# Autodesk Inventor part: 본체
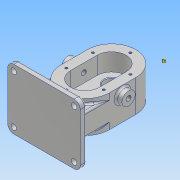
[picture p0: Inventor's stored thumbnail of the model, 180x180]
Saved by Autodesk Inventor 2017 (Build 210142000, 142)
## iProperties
Part Number: 본체
Material: 알루미늄 6061
Document SubType Name: Modeling
Designer: 222
Density: 2.7 g/cm^3
Appearance: 알루미늄 - 평지
Mass: 1442.14 g
Surface Area: 789.865 cm^2
Volume: 534.127 cm^3
Author: 222
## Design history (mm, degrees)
sketch "스케치1"
  geometry: L1 (-40, 0)-(-40, -44); L2 (40, 0)-(40, -44); A1 r 40 centre (0, 0) between (40, 0) and (-40, 0); A2 r 40 centre (0, -44) between (-40, -44) and (40, -44); 1 further point
  constraints: 4 end point, 4 point on circle, 4 tangent, 2 centre point, 1 coincident, 1 vertical alignment
  dimensions: "d7" = 80 diameter of A2; "d8" = 80 diameter of A1; "d9" = 124 dimension on A2 A1
extrude "돌출1" new body sketch "스케치1" distance "d10" = 53; taper "d11" = 0 deg
sketch "스케치2"
  geometry: L1 (-24, 0)-(-24, -44); L2 (24, 0)-(24, -44); A1 r 24 centre (0, 0) between (24, 0) and (-24, 0); A2 r 24 centre (0, -44) between (-24, -44) and (24, -44); 1 further point
  constraints: 4 end point, 4 point on circle, 3 tangent, 2 centre point, 1 coincident, 1 vertical, 1 vertical alignment
  dimensions: "d12" = 48 diameter of A1; "d13" = 48 diameter of A2; "d14" = 92 dimension on A2 A1
extrude "돌출2" cut sketch "스케치2" distance "d15" = 29; taper "d16" = 0 deg
node "작업 평면1"
sketch "스케치4"
  geometry: C1 r 19 at (0, 0); 1 further point
  constraints: 1 centre point, 1 coincident
  dimensions: "d18" = 38 diameter of C1
extrude "돌출3" join sketch "스케치4" distance "d19" = 17; taper "d20" = 0 deg
sketch "스케치5"
  geometry: C1 r 12.5 at (0, 0); 1 further point
  constraints: 1 centre point, 1 coincident
  dimensions: "d21" = 25 diameter of C1
extrude "돌출4" cut sketch "스케치5" distance "d22" = 15; taper "d23" = 0 deg
sketch "스케치6"
  geometry: C1 r 8.5 at (0, 0); 1 further point
  constraints: 1 centre point, 1 coincident
  dimensions: "d24" = 17 diameter of C1
extrude "돌출5" cut sketch "스케치6" stored distance "d25" = 15; taper "d26" = 0 deg
sketch "스케치7"
  geometry: L1 (24, 0)-(24, -44) reference; L2 (-24, -44)-(-24, 0) reference; L3 (-40, 0)-(-40, -44) reference; L4 (40, -44)-(40, 0) reference; C1 r 12.5 at (0, -44); A1 r 24 centre (0, 0) between (24, 0) and (-24, 0) reference; A2 r 24 centre (0, -44) between (-24, -44) and (24, -44) reference; A3 r 40 centre (0, 0) between (40, 0) and (-40, 0) reference; A4 r 40 centre (0, -44) between (-40, -44) and (40, -44) reference; 1 further point
  constraints: 1 centre point, 1 coincident
  dimensions: "d27" = 25 diameter of C1
extrude "돌출6" cut sketch "스케치7" distance "d28" = 15; taper "d29" = 0 deg
sketch "스케치8"
  geometry: C1 r 14 at (0, 0); 1 further point
  constraints: 1 centre point, 1 coincident
  dimensions: "d30" = 28 diameter of C1
extrude "돌출7" cut sketch "스케치8" distance "d31" = 7.3; taper "d32" = 0 deg
node "작업 평면3"
  node "작업 평면2"
sketch "스케치9"
  geometry: L1 (60, 83)-(-60, 83); L2 (-60, 83)-(-60, -17); L3 (-60, -17)-(60, -17); L4 (60, -17)-(60, 83); L5 (-19, -17)-(19, -17) reference; 3 further points
  constraints: 8 end point, 3 midpoint, 2 parallel, 1 coincident, 1 horizontal, 1 perpendicular
  dimensions: "d34" = 120 distance of L3.end L2.end; "d35" = 100 distance of L2.end L1.end
extrude "돌출8" join sketch "스케치9" distance "d36" = 10; taper "d37" = 0 deg
sketch "스케치10"
  geometry: L1 (-40, -45)-(40, -45); L2 (40, -45)-(40, -8); L3 (40, -8)-(-40, -8); L4 (-40, -8)-(-40, -45); L5 (60, 17)-(-60, 17) reference; 3 further points
  constraints: 8 end point, 2 coincident, 2 parallel, 1 horizontal, 1 midpoint, 1 perpendicular, 1 vertical alignment
  dimensions: "d40" = 80 distance of L3.end L2.end; "d41" = 37 distance of L2.end L1.end; "d42" = 25 distance between parallel lines of L5 L3
extrude "돌출9" join sketch "스케치10" stored distance "d43" = 10; taper "d44" = 0 deg
fillet "모깎기1" dims "d45" = 10
sketch "스케치11"
  geometry: L1 (0, 44)-(-53, 44) reference; L2 (-53, 0)-(-53, 44) reference; L3 (-45, 0)-(-53, 0) reference; L4 (-45, -58)-(-45, 0) reference; L5 (-83, -58)-(-45, -58) reference; L6 (-83, -68)-(-83, -58) reference; L7 (17, -68)-(-83, -68) reference; L8 (17, -58)-(17, -68) reference; L9 (-8, -58)-(17, -58) reference; L10 (-45, -58)-(-8, -58) reference; L11 (0, 44)-(0, 0) reference; L12 (0, 0)-(-8, 0) reference; L13 (-8, 0)-(-8, -58) reference; C1 r 11 at (-39, 22)
  constraints: 1 centre point
  dimensions: "d46" = 22 diameter of C1; "d47" = 22 distance from line of C1.centre L1; "d48" = 14 distance from line of L2 C1.centre
extrude "돌출10" join sketch "스케치11" distance "d49" = 10; taper "d50" = 0 deg
sketch "스케치12"
  geometry: C1 r 11 at (0, 0) reference; 2 further points
  constraints: 1 coincident
hole "구멍1" sketch "스케치12" at (0, 0) diameter "d51" = 8.376; stored, may be unused: countersink angle "d55" = 90 deg, drill point angle "d57" = 0 deg; dims "d52" = 20, "d53" = 25, "d54" = 15, "d56" = 27.3
sketch "스케치13" dims "d58" = 62
  geometry: L1 (0, 0)-(0, 31); C1 r 30.5 at (0, -44); A1 r 40 centre (0, -44) between (-40, -44) and (40, -44) reference; 2 further points
  constraints: 3 coincident, 2 end point, 1 centre point, 1 vertical, 1 vertical alignment, 2 other
  dimensions: "d59" = 61 diameter of C1
hole "구멍2" sketch "스케치13" at (0, 31) diameter "d60" = 4.134; stored, may be unused: countersink angle "d64" = 90 deg, drill point angle "d66" = 118 deg; dims "d61" = 10, "d62" = 25, "d63" = 15, "d65" = 12
sketch "스케치14" dims "d70" = 62
  geometry: L1 (0, -44)-(0, -75); A1 r 40 centre (0, -44) between (-40, -44) and (40, -44) reference; 2 further points
  constraints: 2 coincident, 2 end point, 1 vertical, 1 vertical alignment, 2 other
hole "구멍3" sketch "스케치14" at (0, -75) diameter "d71" = 4.134; stored, may be unused: countersink angle "d75" = 90 deg, drill point angle "d77" = 118 deg; dims "d72" = 10, "d73" = 25, "d74" = 15, "d76" = 12
sketch "스케치15"
  geometry: C1 r 4.5 at (-50, -73); C2 r 4.5 at (-50, 7); C3 r 4.5 at (50, 7); C4 r 4.5 at (50, -73); A1 r 10 centre (-50, 7) between (-50, 17) and (-60, 7) reference; A2 r 10 centre (-50, -73) between (-60, -73) and (-50, -83) reference; A3 r 10 centre (50, -73) between (50, -83) and (60, -73) reference; A4 r 10 centre (50, 7) between (60, 7) and (50, 17) reference; 1 further point
  constraints: 4 centre point, 4 coincident
  dimensions: "d81" = 9 diameter of C1; "d82" = 9 diameter of C2; "d83" = 9 diameter of C3; "d84" = 9 diameter of C4
extrude "돌출11" cut sketch "스케치15" stored distance "d85" = 10; taper "d86" = 0 deg
sketch "스케치16"
  geometry: L1 (-50, 17)-(50, 17) reference; L2 (60, 7)-(60, -73) reference; L3 (50, -83)-(-50, -83) reference; L4 (-60, -73)-(-60, 7) reference; L5 (-40, -45)-(-40, -8) reference; L6 (-40, -8)-(40, -8) reference; L7 (40, -8)-(40, -45) reference; L8 (40, -45)-(-40, -45) reference; C1 r 4.5 at (50, 7) reference; C2 r 4.5 at (-50, -73) reference; C3 r 4.5 at (-50, 7) reference; C4 r 4.5 at (50, -73) reference; A1 r 10 centre (-50, 7) between (-50, 17) and (-60, 7) reference; A2 r 10 centre (50, 7) between (60, 7) and (50, 17) reference; A3 r 10 centre (50, -73) between (50, -83) and (60, -73) reference; A4 r 10 centre (-50, -73) between (-60, -73) and (-50, -83) reference; 2 further points
  constraints: 1 other
  dimensions: "d87" = 60 distance from line of point (0, -71) L4; "d88" = 12 distance from line of L3 point (0, -71)
feature "엠보싱1" sketch "스케치16" dims "d7" = 80, "d19" = 17, "d89" = 0.5, "d90" = 0
fillet "모깎기2" dims "d94" = 0.5
chamfer "모따기2" distance "d95" = 0.5; stored, may be unused: second distance "d96" = 2, angle "d97" = 60 deg
fillet "모깎기3" dims "d98" = 3
fillet "모깎기4" dims "d99" = 3
fillet "모깎기5" dims "d100" = 3
fillet "모깎기6" dims "d101" = 3
chamfer "모따기3" distance "d102" = 1; stored, may be unused: second distance "d103" = 2, angle "d104" = 30 deg
chamfer "모따기4" distance "d105" = 1; stored, may be unused: second distance "d106" = 2, angle "d107" = 45 deg
node "솔리드1"
mirror "미러1"
mirror "미러2"
pattern_circular "원형 패턴1" dims angle "d68" = 360 deg
pattern_circular "원형 패턴2" dims angle "d79" = 360 deg
node "투영된 루프1"
node "작업 평면4"
node "절단 모서리 투영1"
node "절단 모서리 투영2"
other parameters: "d17" = 17, "d33" = -152
